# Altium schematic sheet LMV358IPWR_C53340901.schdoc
size 127 x 101 mm
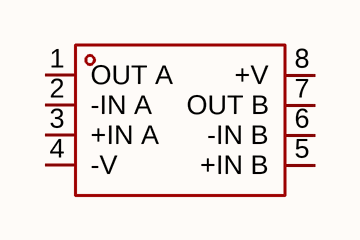
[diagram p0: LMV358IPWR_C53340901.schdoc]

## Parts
U?  lmv358ipwr(tp)  [TSSOP-8_L4.4-W3.0-P0.65-LS6.4-BL-3]  (value not drawn)

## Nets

Not connected (* = marked no-connect by the designer): U? 1(OUT_A) 2(-IN_A) 3(+IN_A) 4(-V) 5(+IN_B) 6(-IN_B) 7(OUT_B) 8(+V)

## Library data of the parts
U? = lmv358ipwr(tp): 放大器数:2;轨到轨:轨到轨输入,轨到轨输出;增益带宽积(GBW):1MHz;输入失调电压(Vos):500uV;压摆率(SR):-;输入偏置电流(Ib):10pA;; Manufacturer: TECH PUBLIC(台舟); AddInBom: yes; SymbolName: LMV358IPWR_C53340901; ModelId: 03fc033f402846a5ab66f50ee4246a8b; ModelTransform: 118.11,251.968,0,0,0,0,0,0,0; Number of Channels: 2; Gain Bandwidth Product: 1MHz; Vos - Input Offset Voltage: 500uV; Input Offset Voltage Drift(Vos TC): 650nV/℃; Ib - Input Bias Current: 10pA; Common Mode Rejection Ratio(CMRR): 95dB; Quiescent Current: 50uA; Output Current: 20mA; Single supply: 2.1V~5.5V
